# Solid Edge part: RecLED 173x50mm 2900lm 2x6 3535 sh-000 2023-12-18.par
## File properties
Author: robert.pupel
Template: iso metric part.par
Last saved by: robert.pupel
Revision: 8
Application: Solid Edge
Gęstość: 0.000 kg/m^3
Dokładność: 0.990
Username: robert.pupel
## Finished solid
Body 1: solid body, 1254 faces, 3251 edges, 2086 vertices.
  Faces by surface: plane 659, cylinder 311, torus 116, cone 88, spline 46, sphere 32, swept 2
  Edges by curve: line 1786, curve on surface 741, circle 432, spline 160, ellipse 132
Bounding box of the edges (mm; curved faces can reach further): 172.200 x 4.950 x 49.500, from (-86.1, -3.45, -24.75) to (86.1, 1.5, 24.75).
Cylindrical faces by radius (mm): R0.15 x24, R0.199 x2, R0.2 x78, R0.2002 x4, R0.2169 x6, R0.25 x24, R0.3 x4, R0.3373 x6, R0.4 x16, R0.4006 x4, R0.4008 x4, R0.525 x4, R0.6 x24, R0.65 x24, R1 x14, R1.05 x12, R1.0894 x4, R1.0991 x8, R1.1 x28, R1.5309 x1, R1.5312 x1, R1.5314 x1, R1.5316 x1, R1.7414 x1, R1.7423 x1, R1.7453 x1, R1.7463 x1, R1.75 x3, R4.6937 x1, R6.6787 x1, R6.7484 x1, R6.9973 x1, R7.349 x1, R9.2334 x1, R9.8311 x1, R9.8455 x1, R12.245 x1, R15.7879 x1
Conical faces (half-angle, radius in mm at the cone's reference point): 0.3913 deg R1.0968 x4, 0.447 deg R1.0952 x4, 0.464 deg R1.0955 x4, 0.5 deg R0.5056 x8, 0.5 deg R1.0082 x8, 1 deg R0.5511 x4, 10 deg R0.2132 x4, 10 deg R0.4132 x4, 15.6748 deg R1.1041 x2, 15.6751 deg R1.1041 x2, 15.7937 deg R1.1267 x2, 15.7938 deg R1.1267 x2, 18.4844 deg R1.0657 x8, 18.9316 deg R0.5099 x4, 19.4337 deg R0.5111 x4, 27.363 deg R0.6214 x4, 40.1968 deg R0.519 x2, 40.228 deg R0.5176 x2, 42.9179 deg R0.4919 x2, 42.9331 deg R0.4916 x2, 45 deg R0.575 x4, 45 deg R0.625 x8
Toroidal faces (ring radius, tube radius in mm): R0.0958 r0.3997 x8, R0.1 r0.2 x2, R0.1075 r0.4 x4, R0.1101 r0.4001 x4, R0.1216 r0.4 x4, R0.1234 r0.4 x4, R0.1634 r0.2287 x2, R0.1641 r0.2287 x2, R0.3286 r0.2001 x2, R0.3702 r0.4 x4, R0.3818 r0.2 x4, R0.4163 r0.3984 x4, R0.4824 r0.2001 x2, R0.4952 r0.2 x2, R0.6008 r0.3968 x4, R0.6009 r0.3969 x4, R0.6227 r0.2 x2, R0.6235 r0.2 x2, R0.8 r0.2 x8, R0.8522 r0.3 x4, R0.9002 r0.2 x2, R0.9018 r0.2 x2, R0.9181 r0.2227 x4, R0.9197 r0.223 x2, R0.9199 r0.223 x2, R0.9663 r0.2263 x2, R0.9665 r0.2263 x2, R1.3 r0.2 x4, R1.327 r1.1 x4, R1.3271 r1.1 x4, R1.8254 r0.13 x12, R1.8741 r0.2175 x2, R1.8987 r0.2 x2
Spherical faces by radius (mm): R0.2 x16, R0.6 x4, R1.7 x12
Planar faces by outward normal: +x 77, +y 27, +z 69, -x 96, -y 97, -z 69, oblique 224
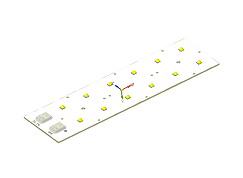
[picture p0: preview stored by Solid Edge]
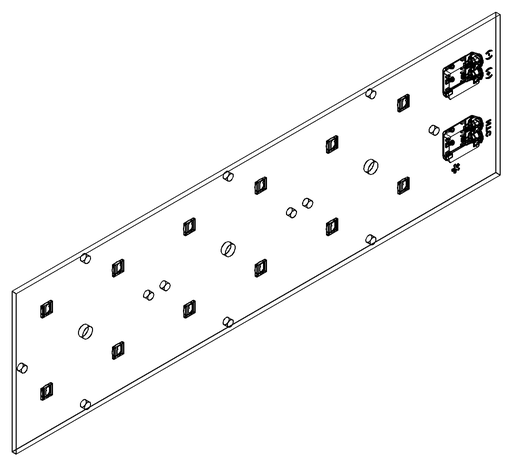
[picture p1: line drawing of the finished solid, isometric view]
